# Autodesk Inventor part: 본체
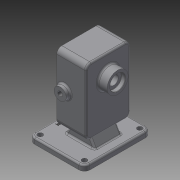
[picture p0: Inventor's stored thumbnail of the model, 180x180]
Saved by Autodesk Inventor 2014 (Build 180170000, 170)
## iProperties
Created: 2020-04
Part Number: 본체
Material: Generic
Document SubType Name: Modeling
Designer: kh
Density: 1 g/cm^3
Appearance: Default
Mass: 544.812 g
Surface Area: 819.925 cm^2
Volume: 544.812 cm^3
Author: kh
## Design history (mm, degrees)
sketch "스케치1"
  geometry: L1 (-50, 60)-(50, 60); L2 (50, 60)-(50, -60); L3 (50, -60)-(-50, -60); L4 (-50, -60)-(-50, 60); L5 (-50, 60)-(50, -60); L6 (50, 60)-(-50, -60); 1 further point
  constraints: 12 end point, 2 midpoint, 2 parallel, 1 horizontal, 1 perpendicular
  dimensions: "d0" = 100 distance of L1.start L1.end; "d1" = 120 distance of L3.end L1.start
extrude "돌출1" new body sketch "스케치1" distance "d2" = 10; taper "d3" = 0 deg
node "작업 평면1"
sketch "스케치2"
  geometry: L1 (0, 60)-(-150, 60); L2 (-150, 20)-(-30, 20); L3 (-30, 20)-(-30, 100); L4 (-30, 100)-(-150, 100); L5 (-150, 100)-(-150, 20)
  constraints: 10 end point, 2 horizontal, 2 parallel, 1 midpoint, 1 perpendicular
  dimensions: "d5" = 150 distance of L1.end L1.start; "d6" = 80 distance of L4.end L2.start; "d7" = 120 distance of L2.start L2.end
extrude "돌출2" join sketch "스케치2" distance "d8" = 53; taper "d9" = 0 deg
sketch "스케치3"
  geometry: L1 (0, 60)-(90, 60); L2 (112, 60)-(68, 60); L3 (112, 84)-(68, 84); L4 (68, 36)-(112, 36); A1 r 24 centre (112, 60) between (112, 36) and (112, 84); A2 r 24 centre (68, 60) between (68, 84) and (68, 36); 1 further point
  constraints: 10 end point, 4 point on circle, 4 tangent, 2 centre point, 1 coincident, 1 collinear, 1 horizontal, 1 midpoint, 1 parallel
  dimensions: "d10" = 90 distance of L1.start L1.end; "d11" = 44 distance of L2.start L2.end; "d12" = 48 diameter of A2
extrude "돌출3" cut sketch "스케치3" distance "d13" = 29; taper "d14" = 0 deg
sketch "스케치4"
  geometry: L1 (68, 84)-(112, 84) reference; L2 (112, 36)-(68, 36) reference; C1 r 12.5 at (112, 60); C2 r 12.5 at (68, 60); A1 r 24 centre (68, 60) between (68, 84) and (68, 36) reference; A2 r 24 centre (112, 60) between (112, 36) and (112, 84) reference; 1 further point
  constraints: 2 centre point, 2 coincident
  dimensions: "d15" = 25 diameter of C1; "d16" = 25 diameter of C2
extrude "돌출4" cut sketch "스케치4" distance "d17" = 15; taper "d18" = 0 deg
chamfer "모따기1" distance "d19" = 1; stored, may be unused: second distance "d20" = 2, angle "d21" = 45 deg
sketch "스케치5"
  geometry: C1 r 12.5 at (-112, 60) reference; C2 r 19 at (-112, 60); 1 further point
  constraints: 1 centre point, 1 coincident
  dimensions: "d22" = 38 diameter of C2
extrude "돌출5" join sketch "스케치5" distance "d23" = 17; taper "d24" = 0 deg
sketch "스케치6"
  geometry: C1 r 19 at (0, 0) reference; C2 r 14 at (0, 0); 1 further point
  constraints: 1 centre point, 1 coincident
  dimensions: "d25" = 28 diameter of C2
extrude "돌출6" cut sketch "스케치6" distance "d26" = 7.3; taper "d27" = 0 deg
chamfer "모따기2" distance "d28" = 0.7; stored, may be unused: second distance "d29" = 2, angle "d30" = 30 deg
fillet "모깎기1" dims "d31" = 0.5
sketch "스케치7"
  geometry: C1 r 13.5 at (0, 0) reference; C2 r 8.5 at (0, 0); 1 further point
  constraints: 1 centre point, 1 coincident
  dimensions: "d32" = 17 diameter of C2
extrude "돌출7" cut sketch "스케치7" stored distance "d33" = 7.3; taper "d34" = 0 deg
sketch "스케치8"
  geometry: L1 (-53, 0)-(-53, 120) reference; L2 (17, -30)-(-83, -30) reference; C1 r 11 at (-39, 60); 2 further points
  constraints: 1 centre point, 1 coincident
  dimensions: "d35" = 14 distance from line of L1 point (-39, 60); "d36" = 90 distance from line of L2 point (-39, 60); "d37" = 22 diameter of C1
extrude "돌출8" join sketch "스케치8" distance "d38" = 8; taper "d39" = 0 deg
hole "구멍1" diameter "d42" = 8.917; stored, may be unused: countersink angle "d46" = 90 deg, drill point angle "d48" = 118 deg; dims "d40" = 10, "d41" = 10, "d43" = 6, "d44" = 4, "d45" = 2, "d47" = 8
fillet "모깎기2" dims "d49" = 10
fillet "모깎기3" dims "d50" = 9
fillet "모깎기4" dims "d51" = 3
sketch "스케치9"
  geometry: L1 (-50, -50)-(-50, 50) reference; L2 (-40, 60)-(40, 60) reference; L3 (50, 50)-(50, -50) reference; L4 (40, -60)-(-40, -60) reference; A1 r 10 centre (-40, -50) between (-50, -50) and (-40, -60) reference; A2 r 10 centre (-40, 50) between (-40, 60) and (-50, 50) reference; A3 r 10 centre (40, 50) between (50, 50) and (40, 60) reference; A4 r 10 centre (40, -50) between (40, -60) and (50, -50) reference; 1 further point
hole "구멍2" sketch "스케치9" at (-40, 50), (-40, -50), (40, -50), (40, 50) diameter "d52" = 9; stored, may be unused: countersink angle "d56" = 90 deg, drill point angle "d58" = 118 deg; dims "d53" = 6, "d54" = 4, "d55" = 2, "d57" = 8
sketch "스케치10"
  geometry: L1 (0, 60)-(90, 60); L2 (141, 91)-(39, 91); L3 (39, 91)-(39, 29); L4 (39, 29)-(141, 29); L5 (141, 29)-(141, 91); L6 (141, 91)-(39, 29); L7 (39, 91)-(141, 29); C1 r 8.5 at (112, 60) reference; C2 r 12.5 at (68, 60) reference; 8 further points
  constraints: 14 end point, 4 coincident, 4 point on line, 2 horizontal, 2 midpoint, 2 parallel, 2 symmetric about line, 1 perpendicular
  dimensions: "d59" = 90 distance of L1.start L1.end; "d60" = 62 distance of L4.end L2.start; "d61" = 102 distance of L3.end L4.end; "d62" = 44 distance of point (68, 29) point (112, 29); "d63" = 22 horizontal distance of L1.end point (112, 29)
hole "구멍3" sketch "스케치10" at (141, 91), (141, 29), (39, 29), (39, 91), (112, 91), (112, 29), (68, 91), (68, 29) diameter "d64" = 4.459; stored, may be unused: countersink angle "d68" = 90 deg, drill point angle "d70" = 118 deg; dims "d65" = 10, "d66" = 4, "d67" = 2, "d69" = 12
sketch "스케치11"
  geometry: L1 (-36.998, 20.739)-(-36.998, -20.739); L2 (-36.998, -20.739)-(-43.002, -20.739); L3 (-43.002, -20.739)-(-43.002, 20.739); L4 (-43.002, 20.739)-(-36.998, 20.739); L5 (-36.998, 20.739)-(-43.002, -20.739); L6 (-36.998, -20.739)-(-43.002, 20.739); L7 (-50, 50)-(-50, -50) reference; L8 (40, 60)-(-40, 60) reference; 2 further points
  constraints: 4 end point, 1 midpoint, 2 other
  dimensions: "d71" = 10 distance from line of point (-40, 0) L7; "d72" = 60 distance from line of point (-40, 0) L8
feature "엠보싱1" sketch "스케치11" dims "d0" = 100, "d1" = 120, "d10" = 90, "d11" = 44, "d12" = 48, "d73" = 0.5, "d74" = 0
sketch "스케치12"
  geometry: L1 (-33, 30)-(20, 30) reference; L2 (40, 10)-(-40, 10) reference; L3 (8.453, 30)-(20, 10); L4 (-21.453, 30)-(-33, 10); L5 (20, 150)-(-33, 150) reference; L6 (-6.5, 30)-(-6.5, 150); 1 further point
  constraints: 6 end point, 4 point on line, 2 midpoint, 1 other
  dimensions: "d75" = 60 deg angle of L2 L3; "d76" = 53 distance of L4.end L3.end
extrude "돌출9" join sketch "스케치12" stored distance "d77" = 48; taper "d78" = 0 deg
fillet "모깎기5" dims "d79" = 3
fillet "모깎기6" dims "d80" = 3
node "솔리드1"
mirror "대칭1"
node "투영된 루프1"
node "투영된 루프2"
node "투영된 루프3"
node "투영된 루프4"
other parameters: "d4" = -17
